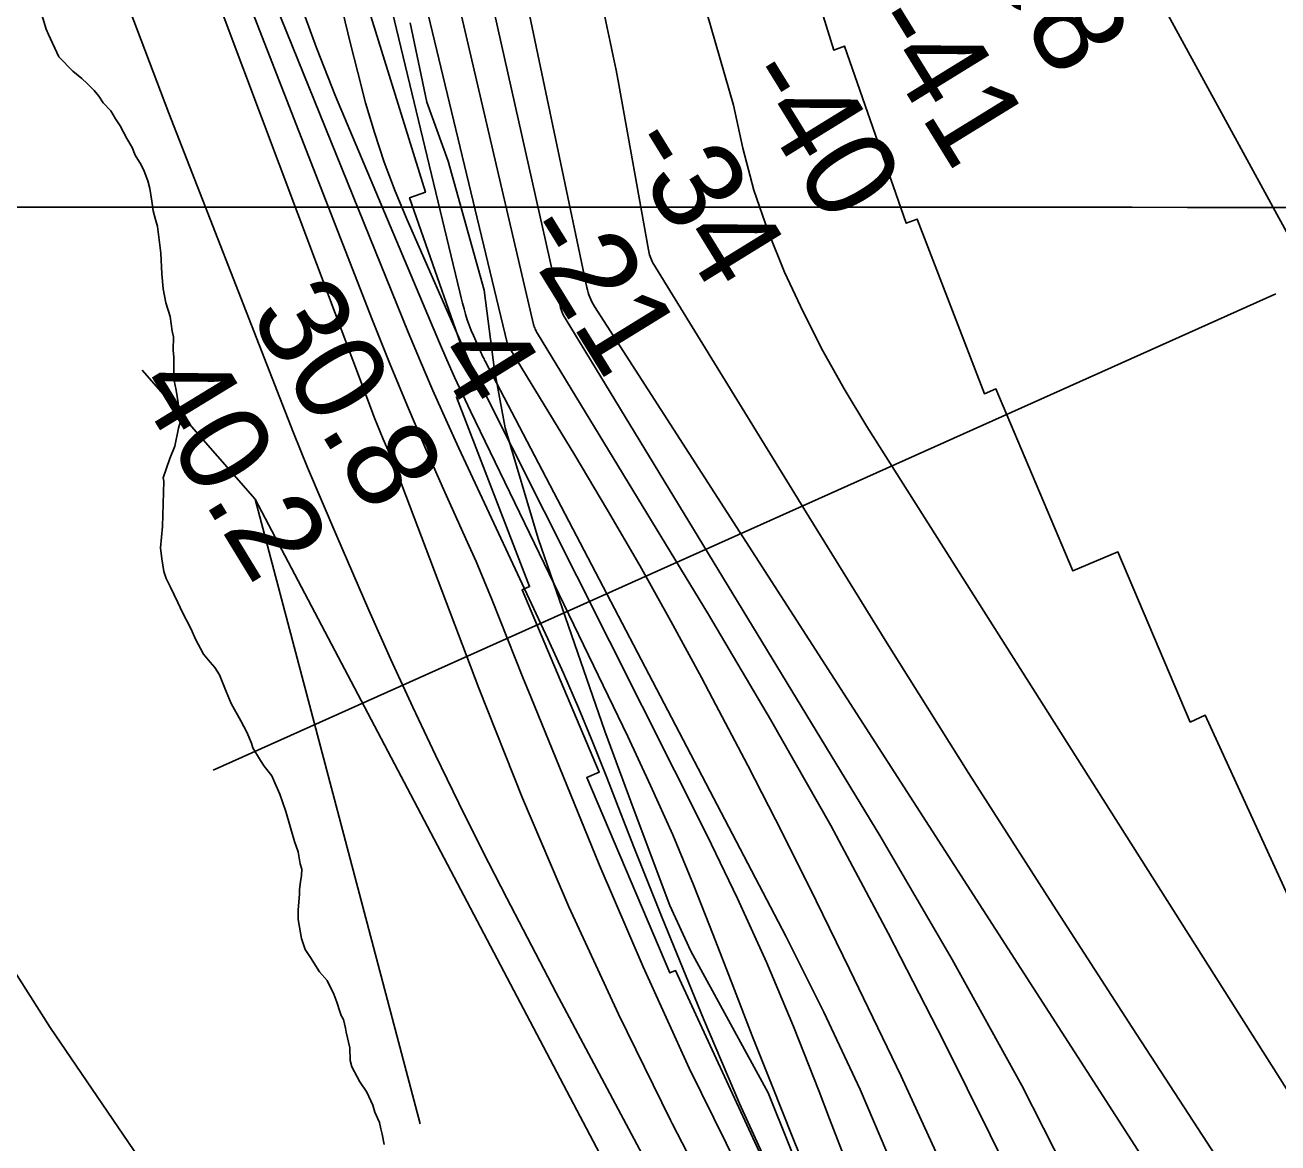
# Model space of a CAD drawing. Extents: x 3263578 to 3301413, y 764927 to 798602.
# Drawn here: x 3276495 to 3277420, y 787260 to 788086 of the extents above; entities that cross this region are included whole.
import ezdxf

# ---------------------------------------------------------------- set-up
doc = ezdxf.new("R2010")
doc.units = 0
for name, color, linetype in [('V-BORW-LINE', 7, 'Continuous'), ('V-GRID-MAJR', 7, 'Continuous'), ('V-RIVR-EDGE', 7, 'Continuous'), ('V-RIVR-RANG', 7, 'Continuous'), ('V-RRAP-RVMT', 7, 'Continuous'), ('V-SITE-VEGE', 7, 'Continuous'), ('V-TOPO-DPTH', 7, 'Continuous'), ('V-TOPO-MAJR', 7, 'Continuous'), ('V-TOPO-MINR', 7, 'Continuous'), ('V-TOPO-WATR', 7, 'Continuous')]:
    doc.layers.add(name, color=color, linetype=linetype)

msp = doc.modelspace()

# ---------------------------------------------------------------- linework, layer by layer
at = {"layer": 'V-BORW-LINE'}
for points in [[(3276379.35, 787556.86), (3276513.59, 787345.4), (3276640.88, 787158.32), (3276718.92, 787029.25), (3276736.24, 786965.54), (3276691.45, 786947.01), (3276632.59, 786991.99), (3276599.34, 787052.02), (3276521.83, 787192.5), (3276452.19, 787318.23)], [(3276452.19, 787318.23), (3276521.83, 787192.5), (3276599.34, 787052.02), (3276632.59, 786991.99), (3276691.45, 786947.01), (3276736.24, 786965.54), (3276718.92, 787029.25), (3276640.88, 787158.32), (3276513.59, 787345.4), (3276379.35, 787556.86)]]:
    msp.add_lwpolyline(points, dxfattribs=at)
at = {"layer": 'V-GRID-MAJR'}
msp.add_spline([(3267732.67, 787953.47), (3270352.8, 787952.61), (3275593.07, 787951.47), (3280833.33, 787951.08), (3286073.6, 787951.47), (3291313.87, 787952.61), (3296554.13, 787954.52), (3299174.27, 787955.75)], degree=3, dxfattribs=at)
at = {"layer": 'V-RIVR-EDGE'}
msp.add_lwpolyline([(3276779.43, 788087.61), (3276791.89, 788028.9), (3276807.43, 787985.39), (3276834.15, 787890.13), (3276841.83, 787830.99), (3276849.55, 787788.38), (3276874.12, 787706.6), (3276923.32, 787564.33), (3276944.91, 787505.6), (3276971.25, 787435.55), (3276986.82, 787401.61), (3277043.94, 787297.14), (3277075.47, 787218.39)], dxfattribs=at)
at = {"layer": 'V-RIVR-RANG'}
msp.add_line((3276634.12, 787535.43), (3277418.78, 787887.42), dxfattribs=at)
at = {"layer": 'V-RRAP-RVMT'}
for points in [[(3277050.78, 788201.48), (3277092.31, 788067.49), (3277100.27, 788070.35), (3277145.81, 787939.54), (3277153.83, 787942.55), (3277203.58, 787813.57), (3277212, 787817.09), (3277268.86, 787682.62), (3277302.17, 787696.72), (3277355.53, 787570.99), (3277366.57, 787576), (3277427.33, 787443.36), (3277452.4, 787454.94), (3277504, 787341.95)], [(3277380.07, 786627.88), (3277352.29, 786676.6), (3277349.78, 786675.34), (3277286.74, 786797.42), (3277289.8, 786799.01), (3277241.58, 786899.2), (3277220.62, 786888.99), (3277170.8, 786989.76), (3277168.06, 786988.49), (3277105.32, 787121.89), (3277099.67, 787119.36), (3277042.2, 787244.29), (3277041.61, 787244.02), (3276975.43, 787387.39), (3276971.16, 787385.64), (3276909.82, 787530.03), (3276919.12, 787534), (3276862.07, 787668.68), (3276867.65, 787671.02), (3276813.61, 787811.03), (3276828.42, 787816.84), (3276779.06, 787958.36), (3276790.79, 787962.43), (3276746, 788107.01)]]:
    msp.add_lwpolyline(points, dxfattribs=at)
at = {"layer": 'V-SITE-VEGE'}
for points in [[(3276507.54, 788093.53), (3276510.75, 788083.01), (3276512.39, 788078.91), (3276520.1, 788062.47), (3276530.27, 788051.78), (3276537.1, 788046.38), (3276541.07, 788042.8), (3276546.16, 788037.46), (3276549.53, 788033.31), (3276552.89, 788028.58), (3276558.55, 788022.64), (3276561.88, 788016.76), (3276565.23, 788011.45), (3276570.21, 788002.05), (3276574.11, 787995.57), (3276576.28, 787989.71), (3276580.74, 787982.64), (3276582.95, 787977.94), (3276585.67, 787970.91), (3276587.27, 787965.08), (3276588.77, 787955.75), (3276589.75, 787948.77), (3276591.33, 787942.35), (3276592.94, 787937.09), (3276595.35, 787917.3), (3276596.13, 787902.2), (3276597.01, 787891.16), (3276599.07, 787880.66), (3276602.3, 787870.72), (3276603.76, 787859.66), (3276604.82, 787855.58), (3276604.57, 787845.72), (3276605.02, 787840.49), (3276604.86, 787834.11), (3276605.17, 787823.08), (3276606.73, 787816.08), (3276608.23, 787806.76), (3276608.67, 787800.95), (3276609.61, 787792.23), (3276608.35, 787788.2), (3276605.7, 787774.92), (3276601.98, 787765.73), (3276596.98, 787751.36), (3276597.5, 787749.03), (3276596.66, 787715.4), (3276595.11, 787699.78), (3276596.06, 787691.63), (3276597.57, 787682.31), (3276599.18, 787677.05), (3276602.5, 787670.59), (3276608.02, 787659.43), (3276611.31, 787651.8), (3276617.39, 787640.05), (3276621.25, 787631.83), (3276624.56, 787625.37), (3276626.78, 787621.25), (3276631.85, 787615.32), (3276635.23, 787611.18), (3276638.58, 787605.87), (3276643.49, 787593.57), (3276647.33, 787584.77), (3276654.55, 787571.83), (3276658.98, 787563.59), (3276662.25, 787555.39), (3276663.33, 787551.89), (3276668.89, 787542.46), (3276671.69, 787538.33), (3276677.31, 787531.23), (3276679.5, 787525.96), (3276683.35, 787517.74), (3276687.67, 787504.87), (3276694.07, 787482.66), (3276696.78, 787475.05), (3276698.3, 787466.32), (3276699.36, 787462.23), (3276699.24, 787457.59), (3276698.55, 787452.97), (3276697.82, 787447.19), (3276697.73, 787443.71), (3276696.87, 787432.13), (3276696.69, 787425.17), (3276699.24, 787411.18), (3276701.94, 787402.99)], [(3276701.94, 787402.99), (3276705.85, 787397.09), (3276712.54, 787386.49), (3276718.18, 787379.96), (3276723.15, 787369.98), (3276725.32, 787364.12), (3276727.46, 787357.11), (3276728.55, 787354.18), (3276730.22, 787351.24), (3276731.8, 787344.82), (3276732.3, 787341.9), (3276734.91, 787330.24), (3276735.26, 787320.95), (3276736.3, 787316.28), (3276742.4, 787305.1), (3276747.43, 787297.44), (3276751.84, 787288.05), (3276753.45, 787282.79), (3276756.73, 787275.16), (3276757.78, 787270.49), (3276758.83, 787266.41), (3276760.39, 787258.83)]]:
    msp.add_lwpolyline(points, dxfattribs=at)
at = {"layer": 'V-TOPO-DPTH'}
for points in [[(3276708, 789101.53), (3277018.29, 788026.62), (3277025.09, 787995.04), (3277033.37, 787963.9), (3277043.87, 787933.45), (3277055.86, 787903.45), (3277069.61, 787874.13), (3277084.21, 787845.26), (3277100.07, 787817.07), (3277116.78, 787789.34), (3277632.66, 786974.56)], [(3277632.66, 786974.56), (3277116.78, 787789.34), (3277100.07, 787817.07), (3277084.21, 787845.26), (3277069.61, 787874.13), (3277055.86, 787903.45), (3277043.87, 787933.45), (3277033.37, 787963.9), (3277025.09, 787995.04), (3277018.29, 788026.62), (3276708, 789101.53)], [(3276703.47, 788357.29), (3276816.18, 787888.51), (3276817.18, 787884.43), (3276818.23, 787880.36), (3276819.32, 787876.31), (3276820.44, 787872.26), (3276821.68, 787868.25), (3276823.03, 787864.28), (3276824.56, 787860.37), (3276826.2, 787856.51), (3276833.23, 787840.9), (3276833.62, 787840.06), (3276834.02, 787839.22), (3276834.43, 787838.39), (3276834.85, 787837.57), (3277056.84, 787412.91), (3277085, 787356.53), (3277111.73, 787299.52), (3277136.34, 787241.56)], [(3276703.47, 788357.29), (3276816.18, 787888.51), (3276817.18, 787884.43), (3276818.23, 787880.36), (3276819.32, 787876.31), (3276820.44, 787872.26), (3276821.68, 787868.25), (3276823.03, 787864.28), (3276824.56, 787860.37), (3276826.2, 787856.51), (3276833.23, 787840.9), (3276833.62, 787840.06), (3276834.02, 787839.22), (3276834.43, 787838.39), (3276834.85, 787837.57), (3277056.84, 787412.91), (3277085, 787356.53), (3277111.73, 787299.52), (3277136.34, 787241.56)], [(3277225, 787231.18), (3277173.58, 787334.87), (3277132.5, 787415.11), (3277090.06, 787494.59), (3277045.57, 787572.95), (3276999.73, 787650.56), (3276873.49, 787858.11), (3276873.04, 787858.89), (3276872.61, 787859.68), (3276872.2, 787860.49), (3276871.82, 787861.31), (3276871.47, 787862.14), (3276871.16, 787862.99), (3276870.9, 787863.85), (3276870.67, 787864.72), (3276780.45, 788251.3)], [(3277225, 787231.18), (3277173.58, 787334.87), (3277132.5, 787415.11), (3277090.06, 787494.59), (3277045.57, 787572.95), (3276999.73, 787650.56), (3276873.49, 787858.11), (3276873.04, 787858.89), (3276872.61, 787859.68), (3276872.2, 787860.49), (3276871.82, 787861.31), (3276871.47, 787862.14), (3276871.16, 787862.99), (3276870.9, 787863.85), (3276870.67, 787864.72), (3276780.45, 788251.3)], [(3276856.52, 788146.55), (3276909.88, 787892.1), (3276910.32, 787890.24), (3276910.83, 787888.4), (3276911.45, 787886.59), (3276912.13, 787884.81), (3276912.9, 787883.06), (3276913.74, 787881.35), (3276914.67, 787879.68), (3276915.66, 787878.05), (3277398.36, 787128.02), (3277424.11, 787088.17), (3277449.94, 787048.38), (3277475.92, 787008.68), (3277501.99, 786969.04), (3277551.76, 786893.62), (3277552.99, 786891.72), (3277554.2, 786889.81), (3277555.37, 786887.87), (3277556.51, 786885.92), (3277563.09, 786874.47), (3278015.87, 785863.69)], [(3276856.52, 788146.55), (3276909.88, 787892.1), (3276910.32, 787890.24), (3276910.83, 787888.4), (3276911.45, 787886.59), (3276912.13, 787884.81), (3276912.9, 787883.06), (3276913.74, 787881.35), (3276914.67, 787879.68), (3276915.66, 787878.05), (3277398.36, 787128.02), (3277424.11, 787088.17), (3277449.94, 787048.38), (3277475.92, 787008.68), (3277501.99, 786969.04), (3277551.76, 786893.62), (3277552.99, 786891.72), (3277554.2, 786889.81), (3277555.37, 786887.87), (3277556.51, 786885.92), (3277563.09, 786874.47), (3278015.87, 785863.69)], [(3277072.48, 787238.29), (3277061.67, 787265.06), (3277046.83, 787302.13), (3277032.14, 787339.24), (3277017.67, 787376.45), (3277003.35, 787413.71), (3276988.66, 787450.81), (3276973.34, 787487.64), (3276957.07, 787524.06), (3276940.17, 787560.21), (3276823.98, 787800.62), (3276818.03, 787813.17), (3276812.21, 787825.79), (3276806.58, 787838.49), (3276801.09, 787851.25), (3276724.26, 788033.5), (3276710.21, 788069.05), (3276697.23, 788104.96)], [(3277461.55, 787869.06), (3277332.11, 788106.44)], [(3277332.11, 788106.44), (3277461.55, 787869.06)], [(3277562.29, 786961.96), (3277312.53, 787345.38), (3277252.04, 787439.05), (3277192.05, 787533.05), (3277132.83, 787627.53), (3277074.1, 787722.32), (3276958.78, 787910.17), (3276958.14, 787911.3), (3276957.57, 787912.46), (3276957.09, 787913.66), (3276956.68, 787914.89), (3276956.33, 787916.15), (3276956.01, 787917.41), (3276955.73, 787918.68), (3276955.48, 787919.96), (3276933.51, 788042.04), (3276931.54, 788052.55), (3276929.48, 788063.04), (3276927.27, 788073.5), (3276924.97, 788083.94), (3276922.64, 788094.38)], [(3277562.29, 786961.96), (3277312.53, 787345.38), (3277252.04, 787439.05), (3277192.05, 787533.05), (3277132.83, 787627.53), (3277074.1, 787722.32), (3276958.78, 787910.17), (3276958.14, 787911.3), (3276957.57, 787912.46), (3276957.09, 787913.66), (3276956.68, 787914.89), (3276956.33, 787916.15), (3276956.01, 787917.41), (3276955.73, 787918.68), (3276955.48, 787919.96), (3276933.51, 788042.04), (3276931.54, 788052.55), (3276929.48, 788063.04), (3276927.27, 788073.5), (3276924.97, 788083.94), (3276922.64, 788094.38)]]:
    msp.add_lwpolyline(points, dxfattribs=at)
at = {"layer": 'V-TOPO-MAJR'}
msp.add_lwpolyline([(3276547.01, 788344.47), (3276750.8, 787801.69), (3276752.91, 787796.2), (3276755.08, 787790.74), (3276757.34, 787785.31), (3276759.66, 787779.91), (3276762.29, 787773.9), (3276763.32, 787771.52), (3276764.33, 787769.12), (3276765.31, 787766.71), (3276766.27, 787764.29), (3276767.21, 787761.87), (3276768.15, 787759.44), (3276769.08, 787757.01), (3276770.01, 787754.58), (3276830.16, 787595.96), (3276862.48, 787514.81), (3276896.56, 787434.44), (3276933.28, 787355.23), (3276971.74, 787276.8), (3276973.01, 787274.33), (3277013.72, 787195.4)], dxfattribs=at)
at = {"layer": 'V-TOPO-MINR'}
for points in [[(3276708, 789101.53), (3277018.29, 788026.62), (3277025.09, 787995.04), (3277033.37, 787963.9), (3277043.87, 787933.45), (3277055.86, 787903.45), (3277069.61, 787874.13), (3277084.21, 787845.26), (3277100.07, 787817.07), (3277116.78, 787789.34), (3277632.66, 786974.56)], [(3276742.42, 788303.68), (3276851.16, 787851.08), (3276851.26, 787850.69), (3276851.38, 787850.31), (3276851.52, 787849.94), (3276851.68, 787849.57), (3276851.85, 787849.21), (3276852.03, 787848.85), (3276852.22, 787848.5), (3276852.42, 787848.15), (3276901.1, 787768.12), (3276925.29, 787727.56), (3276949.01, 787686.74), (3276972.02, 787645.5), (3276994.55, 787604), (3277002.81, 787588.47), (3277028.81, 787538.84), (3277054.41, 787489.01), (3277079.4, 787438.87), (3277103.99, 787388.53), (3277142.05, 787309.36), (3277170.39, 787247.62)], [(3276780.45, 788251.3), (3276870.67, 787864.72), (3276870.9, 787863.85), (3276871.16, 787862.99), (3276871.47, 787862.14), (3276871.82, 787861.31), (3276872.2, 787860.49), (3276872.61, 787859.68), (3276873.04, 787858.89), (3276873.49, 787858.11), (3276999.73, 787650.56), (3277045.57, 787572.95), (3277090.06, 787494.59), (3277132.5, 787415.11), (3277173.58, 787334.87), (3277225, 787231.18)], [(3276608.77, 788234.85), (3276751.42, 787868.48), (3276764.24, 787836.32), (3276777.4, 787804.31), (3276791.06, 787772.5), (3276805.06, 787740.84), (3276821.88, 787703.6), (3276828.1, 787689.52), (3276834.17, 787675.37), (3276840, 787661.12), (3276845.68, 787646.81), (3276851.29, 787632.47), (3276856.94, 787618.15), (3276862.68, 787603.86), (3276868.47, 787589.59), (3276919.14, 787465.69), (3276951.53, 787390.06), (3276985.53, 787315.2), (3277021.97, 787241.5), (3277060.03, 787168.56), (3277310.25, 786707.64), (3277393.07, 786550.74), (3277417.74, 786502.82), (3277846.42, 785769.59)], [(3276818.48, 788198.92), (3276890.23, 787878.38), (3276890.58, 787877.02), (3276890.97, 787875.68), (3276891.45, 787874.36), (3276891.97, 787873.06), (3276892.56, 787871.78), (3276893.18, 787870.52), (3276893.86, 787869.29), (3276894.56, 787868.07), (3277126.19, 787487.25), (3277179.79, 787395.5), (3277231.17, 787302.58), (3277279.24, 787207.89), (3277325.08, 787112.02), (3277407.7, 786931.09), (3277410.45, 786924.76), (3277413.05, 786918.38), (3277415.42, 786911.9), (3277417.64, 786905.37), (3277419.73, 786898.79), (3277421.81, 786892.21)], [(3276856.52, 788146.55), (3276909.88, 787892.1), (3276910.32, 787890.24), (3276910.83, 787888.4), (3276911.45, 787886.59), (3276912.13, 787884.81), (3276912.9, 787883.06), (3276913.74, 787881.35), (3276914.67, 787879.68), (3276915.66, 787878.05), (3277398.36, 787128.02), (3277424.11, 787088.17), (3277449.94, 787048.38), (3277475.92, 787008.68), (3277501.99, 786969.04), (3277551.76, 786893.62), (3277552.99, 786891.72), (3277554.2, 786889.81), (3277555.37, 786887.87), (3277556.51, 786885.92), (3277563.09, 786874.47), (3278015.87, 785863.69)], [(3276667.97, 788131.17), (3276778.07, 787859.1), (3276787.02, 787837.46), (3276796.2, 787815.91), (3276805.72, 787794.51), (3276815.46, 787773.21), (3276881.19, 787632.37), (3276892.7, 787607.03), (3276903.84, 787581.55), (3276914.45, 787555.83), (3276924.7, 787529.96), (3276934.76, 787504.01), (3276944.92, 787478.1), (3276955.22, 787452.24), (3276965.63, 787426.43), (3276996, 787351.68), (3277022.77, 787289.05), (3277051.01, 787227.13)], [(3276569.3, 788105.49), (3276601.38, 788020.71), (3276683.19, 787810.46), (3276693.37, 787784.76), (3276703.74, 787759.15), (3276714.42, 787733.67), (3276725.3, 787708.27), (3276749.07, 787653.7), (3276765.04, 787617.75), (3276781.36, 787581.96), (3276798.21, 787546.41), (3276815.4, 787511.02), (3276833.01, 787475.84), (3276850.83, 787440.76), (3276868.96, 787405.85), (3276887.3, 787371.04), (3277243.02, 786703.37), (3277251.9, 786686.66), (3277260.76, 786669.93), (3277269.58, 786653.19)], [(3276697.23, 788104.96), (3276710.21, 788069.05), (3276724.26, 788033.5), (3276801.09, 787851.25), (3276806.58, 787838.49), (3276812.21, 787825.79), (3276818.03, 787813.17), (3276823.98, 787800.62), (3276940.17, 787560.21), (3276957.07, 787524.06), (3276973.34, 787487.64), (3276988.66, 787450.81), (3277003.35, 787413.71), (3277017.67, 787376.45), (3277032.14, 787339.24), (3277046.83, 787302.13), (3277061.67, 787265.06), (3277072.48, 787238.29)], [(3277461.55, 787869.06), (3277332.11, 788106.44)], [(3276729.81, 788095.57), (3276735.1, 788073.16), (3276740.73, 788050.84), (3276746.58, 788028.57), (3276753.1, 788006.51), (3276760.26, 787984.68), (3276768.41, 787963.2), (3276777.2, 787941.95), (3276819.84, 787845.09), (3276822.41, 787839.38), (3276825.03, 787833.69), (3276827.74, 787828.04), (3276830.51, 787822.42), (3276998.77, 787487.06), (3277021.2, 787440.56), (3277042.65, 787393.63), (3277062.63, 787346.05), (3277081.62, 787298.05), (3277089.23, 787277.91), (3277103.8, 787239.7)], [(3276922.64, 788094.38), (3276924.97, 788083.94), (3276927.27, 788073.5), (3276929.48, 788063.04), (3276931.54, 788052.55), (3276933.51, 788042.04), (3276955.48, 787919.96), (3276955.73, 787918.68), (3276956.01, 787917.41), (3276956.33, 787916.15), (3276956.68, 787914.89), (3276957.09, 787913.66), (3276957.57, 787912.46), (3276958.14, 787911.3), (3276958.78, 787910.17), (3277074.1, 787722.32), (3277132.83, 787627.53), (3277192.05, 787533.05), (3277252.04, 787439.05), (3277312.53, 787345.38), (3277562.29, 786961.96)], [(3276786.87, 787274.26), (3276665.12, 787735.55), (3276581.65, 787830.87)], [(3276581.65, 787830.87), (3276665.12, 787735.55), (3277232.8, 786656.43), (3277234.27, 786653.64), (3277235.74, 786650.84), (3277237.2, 786648.05), (3277238.67, 786645.25), (3277793.72, 785682.17), (3277808.95, 785664.65), (3277825.65, 785648.52), (3277843.33, 785633.33), (3278947.25, 785019.53), (3278951.49, 785017.8), (3278955.64, 785015.91), (3278959.66, 785013.75), (3278963.6, 785011.43), (3280019.89, 784521.33)]]:
    msp.add_lwpolyline(points, dxfattribs=at)
at = {"layer": 'V-TOPO-WATR'}
msp.add_lwpolyline([(3276703.47, 788357.29), (3276816.18, 787888.51), (3276817.18, 787884.43), (3276818.23, 787880.36), (3276819.32, 787876.31), (3276820.44, 787872.26), (3276821.68, 787868.25), (3276823.03, 787864.28), (3276824.56, 787860.37), (3276826.2, 787856.51), (3276833.23, 787840.9), (3276833.62, 787840.06), (3276834.02, 787839.22), (3276834.43, 787838.39), (3276834.85, 787837.57), (3277056.84, 787412.91), (3277085, 787356.53), (3277111.73, 787299.52), (3277136.34, 787241.56)], dxfattribs=at)

# ---------------------------------------------------------------- texts
at = {"layer": 'V-RIVR-RANG'}
for s, rotation, p in [('-38', 301.65036, (3277189.85, 788154.45)), ('-41', 301.65036, (3277114.18, 788086.65)), ('-40', 301.65036, (3277021.2, 788046.91)), ('-34', 301.65036, (3276934.59, 787996.84)), ('-21', 301.65036, (3276856.84, 787932.4)), ('30.8', 301.39833, (3276659.91, 787871.73)), ('4', 301.65036, (3276795.15, 787841.91)), ('40.2', 301.39833, (3276574.68, 787819.42))]:
    msp.add_text(s, height=67, rotation=rotation, dxfattribs=at).set_placement(p)

doc.saveas('drawing.dxf')
